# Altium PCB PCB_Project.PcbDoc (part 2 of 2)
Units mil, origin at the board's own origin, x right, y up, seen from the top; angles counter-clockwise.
Board outline 2890 x 2480 mil, 2 copper layers (Top Layer, Bottom Layer), stack 62 mil thick; 127 components, 89 nets, 394 pads, 87 vias.
Unrouted connection lines stored in the file: 1.
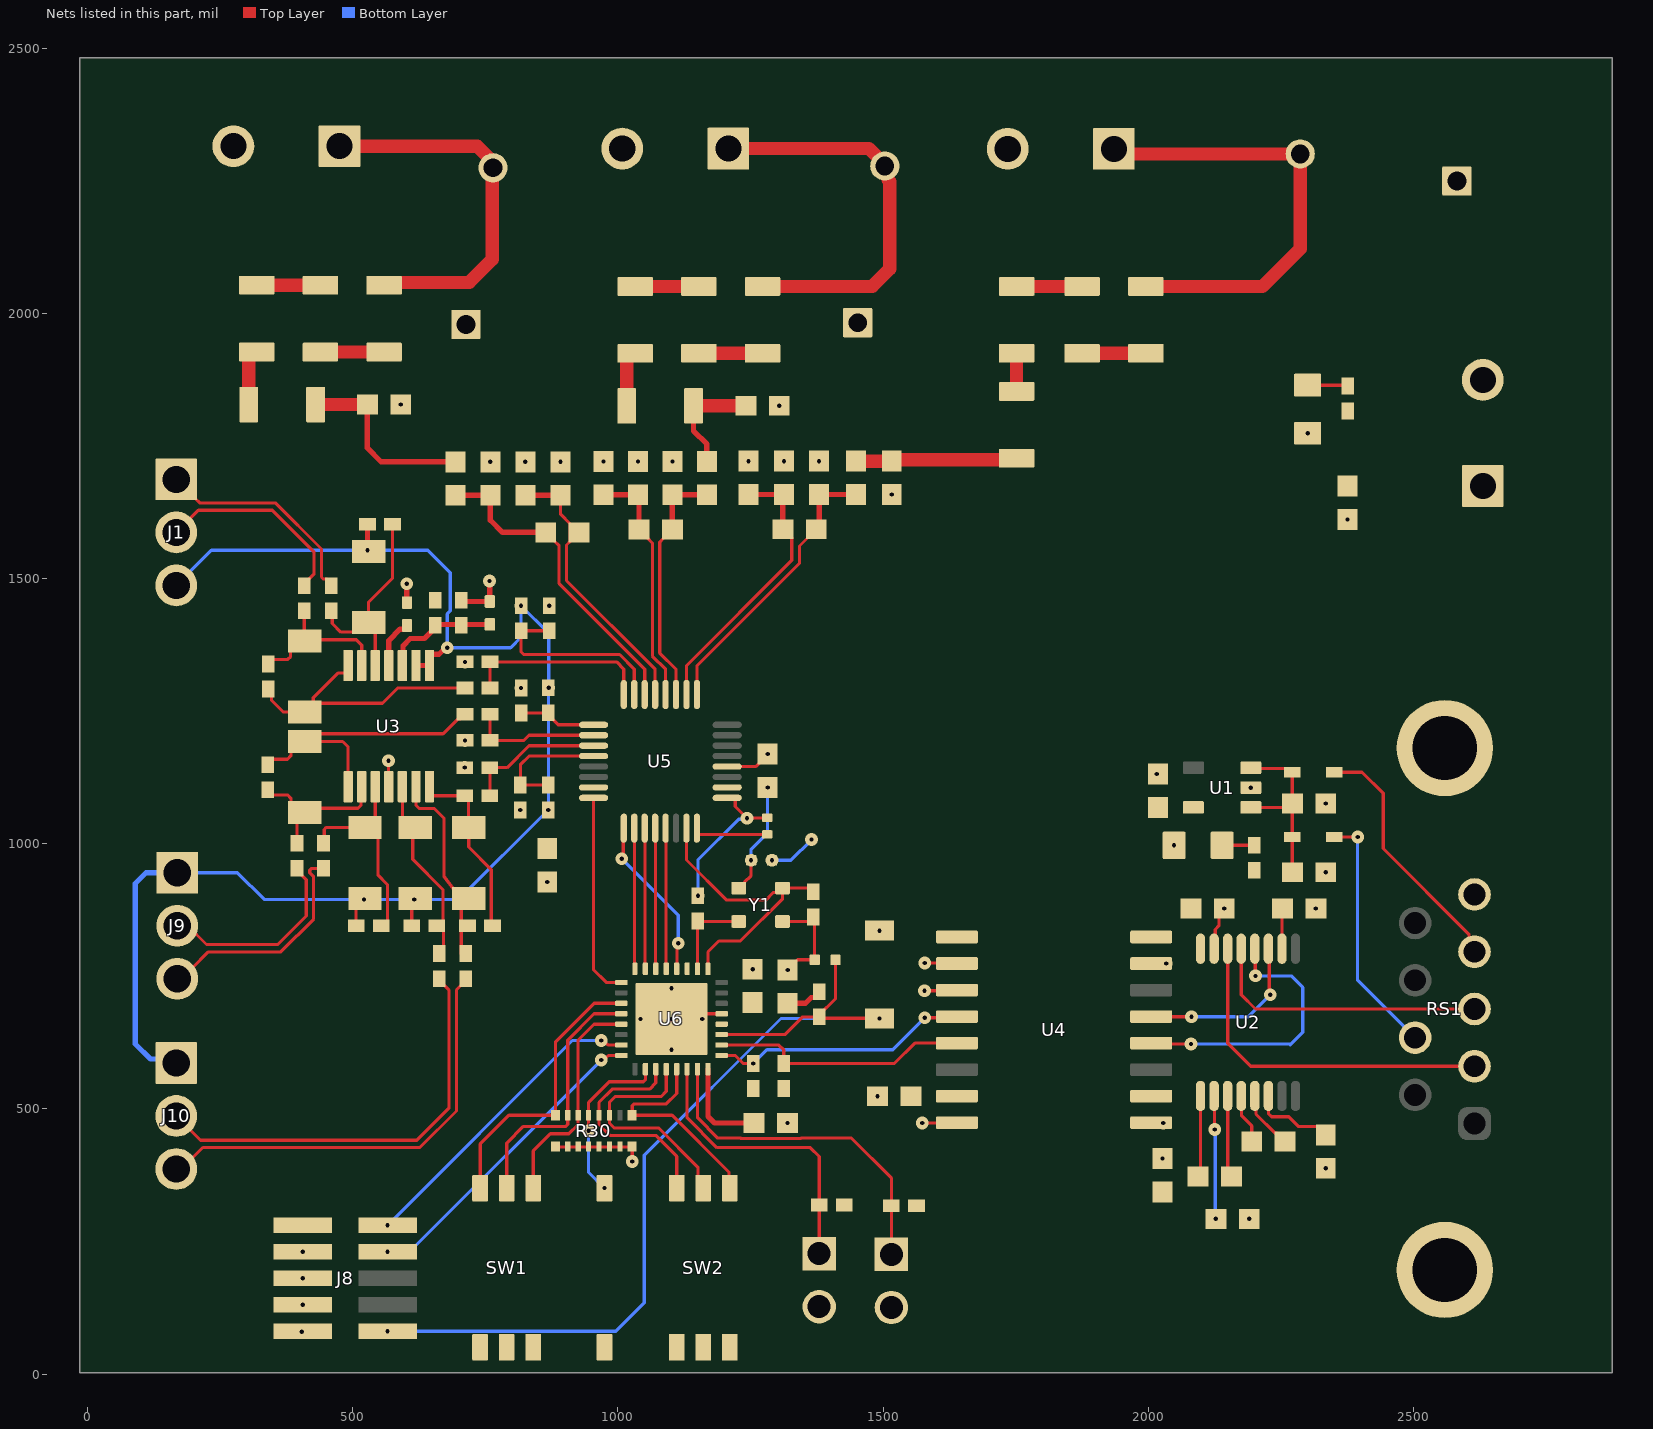
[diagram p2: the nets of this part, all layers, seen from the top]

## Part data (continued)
U3: library part CMP-0128118-1, "Quad, ultra-high-precision (10 μV) zero-drift (0.01 μV/°C) low-input-bias-current op amp 14-TSSOP -40 to 125", Digikey Part Number=296-TLV4387PWRCT-ND, Input Bias Current=60pA, Input Offset Voltage=1uV, Manufacturer="Texas Instruments", Max Dual Supply Voltage=2.75V, Max Supply Voltage=5.5V, Min Dual Supply Voltage=850mV, Min Supply Voltage=1.7V, Mouser Part Number=595-TLV4387PWR, Operating Temperature Range="-40°C to +125°C", Output Current Per Channel=55mA, Voltage Gain=145dB
U4: library part CMP-0094636-1, Digikey Part Number=296-ISO6731DWRCT-ND, Manufacturer="Texas Instruments", Max Supply Voltage=5.5V, Min Supply Voltage=1.71V, Mouser Part Number=595-ISO6731DWR, Operating Temperature Range="-40°C to +125°C"
U5: library part CMP-0085527-2, "8-Channel, 24-Bit, Simultaneously-Sampling, Delta-Sigma ADC, PBS0032A (TQFP-32)", Alternate Manufacturer="Texas Instruments"
U6: library part CMP-0094692-4, "Mixed-Signal Microcontrollers", Frequency_Fixed=80MHz, Manufacturer="Texas Instruments", Max Supply Voltage=3.6V, Min Supply Voltage=1.35V, Operating Temperature Range="-40°C to +125°C"
Y1: library part CMP-0094615-2, "Crystal replacement: Ultra-low Power LVCMOS Oscillator 4-pin, VSON 3.2 x 2.5 x 0.9mm", Frequency Stability=20ppm, Frequency_Fixed=50MHz, Load Capacitance=15pF, Manufacturer="Texas Instruments", Max Supply Current=4mA, Max Supply Voltage=3.465V, Min Supply Voltage=2.375V, Operating Temperature Range="to +135°C", Part Number=CDC6CE05000CDLE

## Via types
v1: diameter 24, hole 8, Top Layer to Bottom Layer, tented both sides, 82 vias
v2: diameter 19.68, hole 7.87, Top Layer to Bottom Layer, 5 vias

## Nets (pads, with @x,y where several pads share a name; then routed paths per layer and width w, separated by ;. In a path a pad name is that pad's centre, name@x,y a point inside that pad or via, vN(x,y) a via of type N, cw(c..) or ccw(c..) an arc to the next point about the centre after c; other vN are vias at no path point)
ACT: J6.1 R20.1 U6.31 | length 649.4
  Top Layer w6: U6.31@1150.12,574.91 1150.12,482.8 1188.1,444.81 1231.55,444.81 1232.58,443.78 1343.95,443.78 1344.98,444.81 1440.35,444.81 1515.49,369.68 R20.1@1515.49,317.28 J6.1@1515.49,225.46
ADS_CS: U5.17 U6.12 | length 312
  Top Layer w6: v1@1011.04,970.79 1009.99,971.84 1009.99,1028.05 U5.17@1011.1,1029.16 ; U6.12@1110.75,763.89 1111.33,764.47 1111.33,809.77 v1(1113.59,812.03)
  Bottom Layer w6: v1(1007.17,971.35) 1113.59,864.92 v1(1113.59,812.03)
ADS_DIN_MSP_DOUT: U5.21 U6.13 | length 265.8
  Top Layer w6: U5.21@1089.84,1029.16 1090.45,1028.55 1090.45,764.5 U6.13@1091.06,763.89
ADS_DOUT_MSP_DIN: U5.20 U6.14 | length 265.8
  Top Layer w6: U5.20@1070.16,1029.16 1070.77,1028.55 1070.77,764.5 U6.14@1071.38,763.89
ADS_DRDY: U5.18 U6.16 | length 265.8
  Top Layer w6: U5.18@1030.79,1029.16 1031.4,1028.55 1031.4,764.5 U6.16@1032.01,763.89
ADS_SYNC_RESET: U5.16 U6.17 | length 386.3
  Top Layer w6: U5.16@954.02,1086.25 954.02,762.25 977.97,738.3 U6.17@1006.42,738.3
GND: C1.2 C4.1 C5.1 C6.2 C9.1 C10.2 C12.1 C14.2 C15.2 C17.1 C23.2 C28.2 C30.2 C33.1 C34.1 C35.1 C38.1 C40.1 C41.1 C44.2 D3.2 J2.2 J3.2 J4.2 J5.2 J6.2 J7.2 J8.3 J8.5 J8.7 J8.9 R8.1 R9.1 R10.1 R16.1 R17.1 R18.1 R26.1 R27.1 R28.1 R30.9 R30.10 R30.11 R30.12 R30.13 R30.14 R30.15 R30.16 R35.1 R36.1 R38.2 R42.1 R44.2 R49.1 R51.2 SW4.1 U3.11 U4.2 U4.3 U4.8 U5.25 U5.28 U6.5 U6.33 Y1.2 | length 1258.4
  Top Layer w6: v1(567.4,1156.13) 567.7,1155.84 567.7,1107.66 U3.11@567.99,1107.36 ; R30.9@877.89,428.25 1026.84,428.25 v1@1026.85,400.75 ; v2(1158.98,669.4) 1158.98,672.4 1165.82,679.24 U6.5@1195.39,679.24 ; U5.25@1205.98,1086.25 1218.58,1086.25 1221.26,1083.56 1221.26,1069.98 v1(1243.39,1047.85) 1243.88,1048.35 1280.88,1048.35 C30.2@1281.38,1048.85 ; U5.28@1205.98,1145.3 1259.64,1145.3 1282.28,1167.94 v1(1282.28,1168.93) ; Y1.2@1310.31,853.17 1359.94,853.17 C6.2@1368.57,861.8 1370.83,859.54 C38.1@1370.83,780.93 1338.98,780.93 1336.69,778.64 1335.7,778.64 1320,762.94 v1(1320,761.96) ; v1(1573.65,473.36) 1638.55,473.36 U4.8@1639.15,473.96 ; v1(1578.03,722.47) 1637.66,722.47 U4.3@1639.15,723.96 ; v1(1578.65,774.82) 1638.28,774.82 U4.2@1639.15,773.96
  Top Layer w10: v1(601.79,1490.16) 602.05,1489.9 602.05,1454.82 C23.2@602.3,1454.56 ; R36.1@704.69,1459.08 707.24,1456.53 C44.2@758.53,1456.53 758.29,1456.77 758.29,1494.79 v1(758.05,1495.03)
  Bottom Layer w6: v1(1150.82,901.52) 1150.82,969.17 1227.6,1045.94 1241.48,1045.94 v1(1243.39,1047.85) ; v1(1290.48,968.56) 1326.12,968.56 v1(1365.17,1007.6)
  other v1: 403.66,79.66 405.53,130.46 405.53,180.46 405.53,230.46 1026.85,400.74 1319.76,473.36 1489.32,523.56 1253.98,763.11 1493.25,835.95 866.71,927.79 816.04,1063.44 711.29,1143.33 711.67,1194.52 817.32,1293.44 711.67,1342.65 870.56,1448.66 2375.71,1611.3 1516.34,1658.17 759.46,1719.82 825.41,1719.83 891.9,1719.83 972.67,1720.71 1037.78,1720.71 1102.67,1720.71 1246.01,1721.16 1312.91,1721.16 1379.33,1721.16 2300.44,1773.74 1304.12,1825.46 590.51,1827.82
  other v2: 1100.91,611.33 1042.83,669.4 1100.91,669.4 1100.91,727.47
GND_ISO_RS: C3.2 C7.2 C8.2 C13.1 C16.1 C20.1 C25.2 D4.2 R29.1 RS1.5 RS1.10 RS1.11 U1.2 U2.15 U4.9 U4.15 | length 83.7
  Top Layer w6: U2.15@2124.04,801.85 2126.28,804.09 2126.28,838.1 2133.06,844.88 2133.06,867.57 v1(2143.14,877.64)
  other v1: 2190.35,292.56 2334.54,387.94 2026.87,406.25 2028.33,473.37 2034.01,773.96 2315.85,877.64 2334.54,946.1 2048.61,996.86 2334.54,1075.59 2193.3,1105.56 2015.8,1131.29
HFXIN: C6.1 U5.23 U6.9 Y1.3 | length 577.1
  Top Layer w6: U5.23@1129.21,1029.16 1129.21,969.11 1204.85,893.48 1278.78,893.48 1293.32,908.01 1302.16,908.01 Y1.3@1310.31,916.16 1361.45,916.16 C6.1@1368.57,909.04 ; U6.9@1169.8,763.89 1169.8,795.87 1190.34,816.4 1230.66,816.4 1310.41,896.15 Y1.3@1310.41,916.06
HFXOUT: C9.2 U6.10 Y1.1 | length 167.3
  Top Layer w6: U6.10@1150.12,763.89 1150.12,841.52 C9.2@1150.82,854.27 1159.63,853.17 Y1.1@1227.64,853.17
IG1: R30.6 SW1.3 U6.21 | length 421.8
  Top Layer w6: SW1.3@840.28,350.46 840.28,420.64 872.7,453.06 907.52,453.06 924.97,470.52 R30.6@924.97,487.99 ; R30.6@924.97,494.68 924.97,629.66 954.87,659.55 U6.21@1006.42,659.55
IG2: R30.7 SW1.2 U6.20 | length 492.9
  Top Layer w6: SW1.2@790.28,350.46 790.28,435.39 821.83,466.94 901.77,466.94 905.29,470.45 R30.7@905.29,487.99 ; R30.7@905.29,490.39 905.29,629.59 954.94,679.24 U6.20@1006.42,679.24
IG4: R30.8 SW1.1 U6.19 | length 536.7
  Top Layer w6: SW1.1@740.28,350.46 740.28,433.86 794.4,487.99 R30.8@882.16,487.99 ; R30.8@882.56,491.34 882.56,626.48 955,698.93 U6.19@1006.42,698.93
IN_Phase_A: C43.2 R51.1 U5.7 | length 367.7
  Top Layer w6: R51.1@870.56,1401.41 C43.2@817.32,1401.41 817.32,1361.75 822.54,1356.53 1003.16,1356.53 1030.79,1328.89 U5.7@1030.79,1281.13
IN_Phase_B: C36.2 R44.1 U5.9 | length 148.5
  Top Layer w6: R44.1@817.32,1246.2 868.1,1246.2 C36.2@868.54,1246.64 868.54,1242.7 887.2,1224.04 U5.9@954.02,1224.04
IN_Phase_C: C27.2 R38.1 U5.12 | length 235.3
  Top Layer w6: C27.2@868.54,1110.69 R38.1@816.03,1110.69 816.03,1148.77 832.25,1164.99 U5.12@954.02,1164.99
IP_Phase_A: C39.2 R35.2 U5.8 | length 354.9
  Top Layer w6: C39.2@758.92,1293.44 R35.2@758.92,1342.65 997.41,1342.65 1011.1,1328.96 U5.8@1011.1,1281.13
IP_Phase_B: C31.2 R49.2 U5.10 | length 248.9
  Top Layer w6: C31.2@758.92,1244.23 R49.2@758.92,1194.52 822.54,1194.52 832.38,1204.36 U5.10@954.02,1204.36
IP_Phase_C: C24.2 R42.2 U5.11 | length 265.8
  Top Layer w6: C24.2@758.53,1090.19 R42.2@758.53,1143.33 790.98,1143.33 832.32,1184.67 U5.11@954.02,1184.67
M0_CLKOUT: U6.11
Meter_RX_PC_TX: RS1.3 U2.13 | length 537.7
  Top Layer w6: U2.13@2175.22,801.85 2175.22,715.08 2202.09,688.22 RS1.3@2615,688.22
Meter_TX_PC_RX: RS1.2 U2.14 | length 661.5
  Top Layer w6: U2.14@2149.63,801.85 2149.63,623.69 2193.11,580.22 RS1.2@2615,580.22
NetC16_2: C16.2 U2.6 | length 157.9
  Top Layer w6: U2.6@2226.4,524.29 2226.4,491.25 2232.78,484.87 2264.93,484.87 2283.37,466.43 2319.04,466.43 C16.2@2334.54,450.93
NetC19_1: C19.1 U2.3 | length 155
  Top Layer w6: U2.3@2149.63,524.29 2149.63,379.49 C19.1@2156.84,372.28
NetC19_2: C19.2 U2.1 | length 153.9
  Top Layer w6: C19.2@2093.84,372.28 2098.45,376.89 U2.1@2098.45,524.29
NetC20_2: C20.2 U2.2 | length 233.1
  Top Layer w6: U2.2@2124.04,524.29 2124.69,523.64 2124.69,461.55 v1(2125.34,460.9)
  Bottom Layer w6: v1(2125.34,460.9) 2126.35,459.9 2126.35,293.57 v1(2127.35,292.56)
NetC21_1: C21.1 U2.5 | length 111.6
  Top Layer w6: U2.5@2200.81,524.29 2203.05,522.05 2203.05,489.97 2239.18,453.84 2242.2,453.84 C21.1@2257.9,438.14
NetC21_2: C21.2 U2.4 | length 94.3
  Top Layer w6: U2.4@2175.22,524.29 2175.95,523.56 2175.95,486.75 2194.91,467.8 C21.2@2194.91,438.14
NetC22_1: C22.1 C39.1 R46.2 U3.7 | length 523.3
  Top Layer w6: R46.2@340.57,1291.47 346.9,1285.13 346.9,1270.24 368.98,1248.17 C22.1@409.88,1248.17 426.45,1264.74 556.02,1264.74 584.71,1293.44 C39.1@711.67,1293.44 ; C22.1@425.7,1263.99 425.7,1275.3 471.92,1321.52 485.36,1321.52 491.22,1327.38 U3.7@491.22,1335.71
NetC22_2: C22.2 R33.2 R46.1 U3.6 | length 301.7
  Top Layer w6: R46.1@340.57,1338.72 349.12,1347.27 377.4,1347.27 382.83,1352.7 382.83,1363.37 401.48,1382.02 C22.2@409.87,1382.02 ; R33.2@408.63,1438.98 408.63,1383.26 C22.2@409.87,1382.02 ; U3.6@516.81,1335.71 516.81,1374.24 506.57,1384.47 412.33,1384.47 C22.2@409.87,1382.02
NetC24_1: C24.1 C37.1 R31.2 U3.14 | length 347.1
  Top Layer w6: U3.14@644.76,1107.36 644.76,1096.05 650.62,1090.19 C24.1@711.29,1090.19 718.45,1083.02 C37.1@718.45,1030.85 ; C37.1@718.68,1030.62 718.68,993.61 761.19,951.11 761.19,850.36 R31.2@765.93,845.62
NetC26_2: C26.2 R34.2 R50.1 U3.5 | length 386.9
  Top Layer w6: R34.2@459.88,1438.98 461.5,1437.35 461.5,1414.99 477.68,1398.81 516.24,1398.81 C26.2@533.05,1415.62 ; C26.2@530,1417.32 530,1455.66 575.14,1500.8 R50.1@575.14,1601.85 ; C26.2@533.05,1405.62 542.4,1396.27 U3.5@542.4,1335.71
NetC29_1: C29.1 C31.1 R39.2 U3.8 | length 579.2
  Top Layer w6: R39.2@339.38,1148.81 339.38,1150.16 348.2,1158.97 377.03,1158.97 383.47,1165.41 383.47,1175.99 400.03,1192.55 C29.1@409.87,1192.55 ; U3.8@491.22,1107.36 491.22,1182.14 480.81,1192.55 C29.1@409.87,1192.55 ; C31.1@711.67,1244.23 702.86,1235.42 698.55,1235.42 670.38,1207.25 424.57,1207.25 C29.1@409.87,1192.55
NetC29_2: C29.2 R39.1 R40.2 U3.9 | length 292.4
  Top Layer w6: R39.1@339.38,1101.57 339.38,1100.4 348.2,1091.59 377.61,1091.59 383.37,1085.83 383.37,1075.35 400.03,1058.69 394.88,1053.54 R40.2@394.88,1000.62 ; C29.2@409.87,1058.69 417.86,1066.68 509.99,1066.68 515.65,1072.35 515.65,1106.21 U3.9@516.81,1107.36
NetC30_1: C30.1 U5.24 | length 142.7
  Top Layer w6: U5.24@1148.9,1029.16 1148.9,1020.03 1151.58,1017.35 C30.1@1281.38,1017.35
NetC32_2: C32.2 R41.2 R43.1 U3.10 | length 366.1
  Top Layer w6: R41.2@444.87,1000.62 446.4,1002.14 446.4,1026.69 450.33,1030.62 C32.2@523.05,1030.62 ; C32.2@528.75,1030.62 547.4,1011.97 547.4,940.94 565.42,922.92 565.42,852.56 R43.1@558.49,845.62 ; C32.2@542.4,1049.28 U3.10@542.4,1107.36
NetC37_2: C37.2 R31.1 R47.2 U3.13 | length 380.1
  Top Layer w6: U3.13@619.17,1107.36 619.25,1107.29 619.25,1072.35 625.33,1066.27 653.69,1066.27 672.1,1047.85 672.1,937.78 690.19,913.9 C37.2@704.69,898.7 ; R47.2@704.69,791.84 704.69,845.46 C37.2@704.69,898.7 ; C37.2@718.68,896.76 C37.2@704.69,898.7
NetC42_2: C42.2 R37.1 R48.2 U3.12 | length 361.4
  Top Layer w6: U3.12@593.58,1107.36 593.58,1049.28 612.24,1030.62 613.05,1030.62 613.05,970.29 670.16,913.18 670.16,854.27 663.78,847.88 661.05,847.88 R37.1@658.62,845.46 ; R37.1@662.27,846.66 671.25,837.68 671.25,800.59 R48.2@663.4,792.74
NetC44_1: C44.1 R32.1 R36.2 U3.3 | length 221
  Top Layer w10: U3.3@593.58,1335.71 594.79,1336.92 594.79,1372.96 608.4,1386.57 635.02,1386.57 648.64,1400.19 648.64,1405.03 656.84,1413.22 704.69,1413.22 C44.1@758.53,1413.22
NetD3_1: D3.1 R6.1 | length 75.8
  Top Layer w6: D3.1@2300.44,1864.29 2374.33,1864.29 R6.1@2375.71,1862.91
NetD4_1: D4.1 R7.1 | length 61
  Top Layer w6: D4.1@2139.16,996.86 R7.1@2200.14,996.86
NetJ1_1: J1.1 R34.1 | length 409.1
  Top Layer w6: J1.1@167.21,1686.85 203.58,1650.48 211.54,1642.51 353.93,1642.51 441,1555.44 441,1502.49 444.51,1498.97 451.06,1498.97 459.87,1490.16 R34.1@459.87,1486.22
NetJ1_2: J1.2 R33.1 | length 381.1
  Top Layer w6: J1.2@167.21,1586.85 209,1628.64 348.18,1628.64 427.12,1549.7 427.12,1508.65 408.63,1490.16 R33.1@408.63,1486.22
NetJ2_1: J2.1 R1.2 R8.2 | length 707.4
  Top Layer w25: J2.1@475,2315 734.76,2315 758.7,2291.06 758.7,2280.03 R8.2@764.46,2274.27 ; R1.2@559.02,2052.82 564.23,2058.04 719.55,2058.04 763.05,2101.54 R8.2@763.05,2271.96
NetJ3_1: J3.1 R11.2 R16.2 | length 756.2
  Top Layer w25: J3.1@1208.13,2310.43 1473.5,2310.43 1503.2,2280.72 R16.2@1503.2,2277.52 ; R11.2@1272.63,2050.46 1479.72,2050.46 1512.7,2083.45 1512.7,2247.82 1508.97,2251.56 R16.2@1508.97,2273.78
NetJ7_1: J7.1 R21.2 R26.2 | length 810.4
  Top Layer w25: 1975.47,2300.46 R26.2@2286.47,2300.46 2286.47,2121.46 2215.47,2050.46 R21.2@1995.47,2050.46
NetJ9_2: J9.2 R40.1 | length 377.3
  Top Layer w6: J9.2@169.18,845.17 188.86,845.17 224.26,809.77 358.67,809.77 412.39,863.48 412.39,931.93 394.88,949.44 R40.1@394.88,953.38
NetJ9_3: J9.3 R41.1 | length 437.6
  Top Layer w6: J9.3@169.18,745.17 169.18,764.85 196.9,764.85 227.91,795.87 364.39,795.87 426.26,857.74 426.26,937.68 419.04,944.89 419.04,949.86 422.56,953.38 R41.1@444.88,953.38
NetJ10_2: J10.2 R48.1 | length 810
  Top Layer w6: J10.2@167.21,486.54 212.88,440.87 620.89,440.87 681.72,501.71 681.72,723.24 672.21,732.75 663.4,741.56 R48.1@663.4,745.5
NetJ10_3: J10.3 R47.1 | length 830.4
  Top Layer w6: J10.3@167.21,386.54 176.93,386.54 217.39,427 626.63,427 695.6,495.96 695.6,724.28 712.88,741.56 R47.1@712.88,745.5
NetR1_1: R1.1 R2.2 | length 120
  Top Layer w25: R2.2@439.02,1926.84 R1.1@559.02,1926.84
NetR2_1: R2.1 R3.2 | length 120
  Top Layer w25: R3.2@319.02,2052.82 R2.1@439.02,2052.82
NetR3_1: R3.1 R4.2 | length 111
  Top Layer w25: R4.2@304.02,1827.82 304.02,1921.62 309.23,1926.84 R3.1@319.02,1926.84
NetR4_1: R4.1 R5.1 R9.2 | length 356.5
  Top Layer w10: R9.2@527.52,1827.82 527.52,1746.07 553.76,1719.83 R5.1@693.84,1719.83
  Top Layer w25: R4.1@430,1827.82 R9.2@527.52,1827.82
NetR11_1: R11.1 R12.2 | length 120
  Top Layer w25: R12.2@1152.63,1924.48 R11.1@1272.63,1924.48
NetR12_1: R12.1 R13.2 | length 120
  Top Layer w25: R13.2@1032.63,2050.46 R12.1@1152.63,2050.46
NetR13_1: R13.1 R14.2 | length 111.9
  Top Layer w25: R14.2@1016.64,1825.46 1016.64,1919.26 1021.86,1924.48 R13.1@1032.63,1924.48
NetR14_1: R14.1 R15.1 R17.2 | length 213.6
  Top Layer w10: R14.1@1142.63,1825.46 1142.63,1778.12 1167.63,1753.12 R15.1@1167.63,1720.71
  Top Layer w25: R14.1@1142.63,1825.46 R17.2@1241.13,1825.46
NetR21_1: R21.1 R22.2 | length 120.5
  Top Layer w25: R22.2@1875,1924.48 R21.1@1995.47,1924.48
NetR22_1: R22.1 R23.2 | length 123.3
  Top Layer w25: R23.2@1751.69,2050.46 R22.1@1875,2050.46
NetR23_1: R23.1 R24.2 | length 71.8
  Top Layer w25: R24.2@1751.69,1852.66 R23.1@1751.69,1924.48
NetR24_1: R24.1 R25.1 R27.2 | length 309.6
  Top Layer w25: R25.1@1448.54,1721.16 1448.54,1724.11 1451.49,1721.16 R27.2@1516.34,1721.16 1519.1,1723.92 1748.93,1723.92 R24.1@1751.69,1726.68
NetR29_2: R29.2 U2.10 | length 76.1
  Top Layer w6: U2.10@2251.99,801.85 2251.99,876.78 R29.2@2252.85,877.64
nRST: C38.2 J8.10 R45.1 SW4.2 U6.3 | length 1767.8
  Top Layer w6: U6.3@1195.39,639.87 1314.67,639.87 1348.13,673.33 R45.1@1379.91,673.33 ; C38.2@1410.2,780.93 1410.2,707.56 1379.91,677.27 R45.1@1379.91,673.33 ; SW4.2@1493.25,670.59 1382.65,670.59 R45.1@1379.91,673.33
  Bottom Layer w6: v1(565.77,80.46) 995.89,80.46 1049.73,134.3 1049.73,412.53 1307.49,670.3 v1(1493.25,670.3)
REACT: J5.1 R19.1 U6.30 | length 554.5
  Top Layer w6: U6.30@1130.43,574.91 1130.43,482.86 1186.5,426.79 1362.76,426.79 1379.49,410.07 R19.1@1379.49,318.65 J5.1@1379.49,226.84
RS232_PORT_DTR: D1.2 RS1.4 | length 479
  Top Layer w6: D1.2@2350.29,1134.71 2402.98,1134.71 2442.8,1094.9 2442.8,990.71 2604.38,829.13 2604.38,806.83 RS1.4@2615,796.22
RS232_PORT_RTS: D2.2 RS1.7 | length 467.5
  Top Layer w6: D2.2@2350.29,1012.48 v1(2394.69,1012.48)
  Bottom Layer w6: v1(2394.69,1012.48) 2394.69,742.52 RS1.7@2503,634.22
Serial_RX: R53.1 U4.5 U6.2 | length 489.1
  Top Layer w6: U6.2@1195.39,620.19 1303.51,620.19 1312.65,611.05 R53.1@1312.65,585.46 1521.34,585.46 1559.84,623.96 U4.5@1639.15,623.96
Serial_RX_ISO: U2.12 U4.12 | length 531.6
  Top Layer w6: U4.12@2005.29,623.96 2007.15,622.09 v1(2080.5,622.09) ; U2.12@2200.81,801.85 2201.45,801.21 2201.45,751.29 v1(2202.09,750.65)
  Bottom Layer w6: v1(2080.5,622.09) 2266.32,622.09 2267.74,620.67 2291.18,644.11 2291.18,728.97 2269.5,750.65 v1(2202.09,750.65)
Serial_TX: R52.1 U4.4 U6.1 | length 486.6
  Top Layer w6: U6.1@1195.39,600.5 1221.26,600.5 1236.3,585.46 v1(1255,585.46) ; v1(1578.65,671.62) 1636.81,671.62 U4.4@1639.15,673.96
  Bottom Layer w6: v1(1255,585.46) 1280.87,611.33 1518.36,611.33 v1(1578.65,671.62)
Serial_TX_ISO: U2.11 U4.13 | length 330.1
  Top Layer w6: U4.13@2005.29,673.96 2005.61,673.63 v1(2081.4,673.63) ; U2.11@2226.4,801.85 2228.14,800.11 2228.14,716.82 v1(2229.87,715.08)
  Bottom Layer w6: v1(2081.4,673.63) 2188.42,673.63 v1(2229.87,715.08)
SPI_SCK: U5.19 U6.15 | length 265.8
  Top Layer w6: U5.19@1050.47,1029.16 1051.08,1028.55 1051.08,764.5 U6.15@1051.69,763.89
SW_INT: R30.5 SW3.1 U6.26 | length 319.1
  Top Layer w6: v1@944.62,458.76 R30.5@944.62,487.95 ; R30.5@944.66,487.99 944.66,512.1 983.52,550.96 1048.18,550.96 1051.69,554.48 U6.26@1051.69,574.91
  Bottom Layer w6: v1(944.59,458.73) 944.59,380.37 v1(974.5,350.46)
SWCLK: J8.4 U6.24 | length 593.9
  Top Layer w6: v1(968.52,591.92) 973.39,591.92 981.97,600.5 U6.24@1006.42,600.5
  Bottom Layer w6: v1(565.77,230.46) 607.06,230.46 v1(968.52,591.92)
SWDIO: J8.2 U6.23 | length 588.5
  Top Layer w6: v1(968.52,628.8) 973.39,628.8 982.01,620.19 U6.23@1006.42,620.19
  Bottom Layer w6: v1(565.77,280.46) 914.11,628.8 v1(968.52,628.8)
TPS709_IN: C3.1 C8.1 D1.1 D2.1 U1.1 U1.3 | length 351.6
  Top Layer w6: U1.1@2193.3,1068.16 2264.12,1068.16 C8.1@2271.55,1075.59 ; U1.3@2193.3,1142.97 2194.7,1141.56 2264.7,1141.56 D1.1@2271.55,1134.71 C8.1@2271.55,1075.59 ; C3.1@2271.55,946.1 D2.1@2271.55,1012.48 C8.1@2271.55,1075.59
V_Phase_A_N: C2.2 C4.2 R10.2 U5.5 | length 545.1
  Top Layer w6: R10.2@891.9,1656.83 891.9,1620.75 910.11,1602.55 C2.2@910.11,1571.15 ; C2.2@926.79,1586.85 925.81,1586.85 C2.2@910.11,1571.15 ; U5.5@1070.16,1281.13 1070.16,1328.77 903.02,1495.9 903.02,1563.08 910.11,1570.16 C2.2@910.11,1571.15
  Top Layer w10: C4.2@825.41,1656.83 R10.2@891.9,1656.83
V_Phase_A_P: C1.1 C2.1 R5.2 U5.6 | length 610.1
  Top Layer w6: C2.1@863.8,1586.85 864.78,1586.85 880.49,1571.15 880.49,1570.16 889.15,1561.5 889.15,1490.16 1050.47,1328.83 U5.6@1050.47,1281.13
  Top Layer w10: R5.2@693.84,1656.84 C1.1@759.46,1656.83 759.46,1609.75 782.36,1586.85 C2.1@863.8,1586.85
V_Phase_B_N: C11.2 C12.2 R18.2 U5.4 | length 463.8
  Top Layer w6: C11.2@1039.67,1592.23 1040.66,1592.23 1056.36,1576.53 1056.36,1575.55 1065.04,1566.87 1065.04,1353.5 1089.84,1328.7 U5.4@1089.84,1281.13
  Top Layer w10: R18.2@972.67,1657.72 C12.2@1037.78,1657.72 1039.67,1655.82 C11.2@1039.67,1592.23
V_Phase_B_P: C10.1 C11.1 R15.2 U5.3 | length 464.6
  Top Layer w6: C11.1@1102.67,1592.23 1101.68,1592.23 1085.98,1576.53 1085.98,1575.55 1078.91,1568.48 1078.91,1359.25 1109.53,1328.64 U5.3@1109.53,1281.13
  Top Layer w10: C11.1@1102.67,1592.23 C10.1@1102.67,1657.72 R15.2@1167.63,1657.72
V_Phase_C_N: C17.2 C18.2 R28.2 U5.2 | length 534.4
  Top Layer w6: U5.2@1129.21,1281.13 1129.21,1335.54 1327.61,1533.94 1327.61,1573.47 ; C18.2@1310.9,1592.68 1311.89,1592.68 1327.59,1576.98 1327.59,1573.48
  Top Layer w10: R28.2@1246.01,1658.17 C17.2@1312.91,1658.17 1310.9,1656.16 C18.2@1310.9,1592.68
V_Phase_C_P: C15.1 C18.1 R25.2 U5.1 | length 541.7
  Top Layer w6: U5.1@1148.9,1281.13 1148.9,1334.93 1342.4,1528.44 1342.4,1561.19 C18.1@1373.9,1592.68
  Top Layer w10: C18.1@1373.9,1592.68 1379.33,1598.11 C15.1@1379.33,1658.17 R25.2@1448.54,1658.17
VCC: C5.2 C14.1 C23.1 C28.1 C34.2 C35.2 C40.2 C41.2 J4.1 J8.1 R6.2 R19.2 R20.2 R32.2 R45.2 R52.2 R53.2 SW1.4 SW1.5 SW1.6 SW2.4 SW2.5 SW2.6 SW3.2 U3.4 U4.1 U4.7 U5.15 U5.26 U6.4 Y1.4 | length 379.2
  Top Layer w6: Y1.4@1227.64,916.16 1229.6,916.16 1238.42,924.97 1238.42,926.94 1251.11,939.63 v1(1251.11,968.56)
  Top Layer w10: U3.4@567.99,1335.71 567.99,1383.1 589.34,1404.44 597.46,1404.44 602.3,1409.28 C23.1@602.3,1411.25 ; C35.2@1320,698.97 1353.7,698.97 1364.57,709.83 1373.1,709.83 1379.91,716.64 R45.2@1379.91,720.58
  Bottom Layer w6: v1(1251.11,968.56) 1251.11,989.3 1282.28,1020.48 v1(1282.28,1105.93)
VCC_ISO_RS: C7.1 C13.2 C25.1 R7.2 U1.5 U2.16 U4.10 U4.16
VCM: C26.1 C27.1 C32.1 C36.1 C42.1 C43.1 J1.3 J9.1 J10.1 R37.2 R43.2 R50.2 U3.1 U3.2 | length 2853
  Top Layer w6: R43.2@506.38,845.46 506.38,880.09 v1(521.08,894.79) C32.1@523.05,896.76 ; R37.2@611.38,845.46 611.38,890.09 v1(616.09,894.79) C42.1@618.06,896.76
  Top Layer w10: C26.1@527.9,1553.29 R50.2@527.9,1601.85 ; U3.2@619.17,1335.71 U3.1@644.77,1335.71 644.77,1352.97 648.62,1356.83 662.1,1356.83 674.44,1369.17 v1(678.23,1369.17)
  Bottom Layer w6: J1.3@150.17,1486.85 J1.3@167.21,1486.85 233.51,1553.15 v1(528.03,1553.15) 641.78,1553.15 683.93,1511 683.93,1438.84 678.23,1433.14 v1(678.23,1369.17) 797.58,1369.17 817.32,1388.92 v1(817.32,1448.65) 869.48,1396.5 v1(869.48,1294.08) 869.01,1293.61 869.01,1063.91 v1(868.54,1063.44) 699.89,894.79 v1(616.09,894.79) v1(521.08,894.79) 332.88,894.79 282.5,945.17 J9.1@169.18,945.17
  Bottom Layer w10: J10.1@167.21,586.54 159.88,593.87 118.7,593.87 90,622.57 90,924.83 110.33,945.17 J9.1@169.18,945.17
VCORE: C33.2 U6.32 | length 181.4
  Top Layer w10: U6.32@1169.8,574.91 1169.8,485.56 1182.01,473.36 C33.2@1256.77,473.36
VG1: R30.1 SW2.3 U6.29 | length 415.2
  Top Layer w6: R30.1@1026.84,487.99 1102.1,487.99 1209.14,380.95 1209.14,352.16 SW2.3@1210.84,350.46 ; R30.1@1026.89,487.99 1026.89,505.83 1030.4,509.34 1091.29,509.34 1110.75,528.8 U6.29@1110.75,574.91
VG2: R30.3 SW2.2 U6.28 | length 441.9
  Top Layer w6: U6.28@1091.06,574.91 1091.06,532.76 1081.52,523.21 995.01,523.21 984.03,512.23 R30.3@984.03,487.99 984.03,472.56 992.82,463.76 1076.89,463.76 1150.82,389.83 1150.82,360.48 SW2.2@1160.84,350.46
VG4: R30.4 SW2.1 U6.27 | length 421.3
  Top Layer w6: U6.27@1071.38,574.91 1071.38,548.81 1059.66,537.09 989.26,537.09 964.34,512.17 964.34,470.37 984.82,449.89 1071.14,449.89 1110.84,410.19 SW2.1@1110.84,350.46
pads on no net: J8.6 J8.8 R30.2 RS1.1 RS1.6 RS1.8 RS1.9 U1.4 U2.7 U2.8 U2.9 U4.6 U4.11 U4.14 U5.13 U5.14 U5.22 U5.27 U5.29 U5.30 U5.31 U5.32 U6.6 U6.7 U6.8 U6.18 U6.22 U6.25

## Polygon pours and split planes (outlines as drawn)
VCC_ISO_RS on Top Layer "TOP_LAYER_VCC_ISO_RS_P003" (solid, remove dead copper, pour order 3): 2869.5,1248.46 2815.1,1302.86 2070.49,1302.86 2009.42,1241.79 2009.42,81.33 2074.8,15.95 2826.99,15.95 2869.5,58.46
VCC on Top Layer "TOP_LAYER_VCC_P001" (solid, remove dead copper, pour order 1): 1630.66,1370.32 1728.8,1468.46 2829.5,1468.46 2869.5,1508.46 2869.5,2388.46 2819.5,2438.46 339.5,2438.46 220.07,2319.03 205.23,99.86 294.5,8.46 1556.46,8.46 1630.66,82.66
GND_ISO_RS on Bottom Layer "BOTTOM_LAYER_GND_ISO_RS_P004" (solid, remove dead copper, pour order 4): 2869.5,1248.46 2815.1,1302.86 2070.49,1302.86 2009.42,1241.79 2009.42,81.33 2074.8,15.95 2826.99,15.95 2869.5,58.46
GND on Bottom Layer "BOTTOM_LAYER_GND_P002" (solid, remove dead copper, pour order 2): 1630.66,1370.32 1728.8,1468.46 2829.5,1468.46 2869.5,1508.46 2869.5,2388.46 2819.5,2438.46 339.5,2438.46 220.07,2319.03 205.23,99.86 294.5,8.46 1556.46,8.46 1630.66,82.66

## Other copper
Top Layer:
  pour cut-out: 1119.5,978.46 1129.85,988.81 1433.16,988.81 1443.09,978.88 1443.09,838.04 1396.78,803.07 1297.89,803.07 1205.44,803.07 1175.68,773.31 1135.53,773.31 1117.97,790.87
Bottom Layer:
  pour cut-out: 1119.53,978.49 1129.88,988.84 1433.19,988.84 1443.12,978.91 1443.12,838.04 1396.78,803.07 1205.44,803.07 1175.71,773.34 1135.56,773.34 1118,790.9

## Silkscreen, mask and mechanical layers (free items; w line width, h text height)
Top Overlay:
  text "GND" at 2838.5,1843.16 h20 r90
  text "TIDA-011013" at 2140.67,1793.72 h50 r270
  text "I_A_P" at 329.5,1718.35 h20
  text "I_A_N" at 330.45,1658.78 h20
  text "+3V3" at 2836.3,1631.74 h20 r90
  text "VCM" at 332.96,1581.55 h30
  text "VCM" at 350.37,822.4 h30
  text "I_B_P" at 345.38,768.55 h20
  text "I_B_N" at 344.37,703.3 h20
  text "VCM" at 338.88,567.84 h30
  text "I_C_N" at 335.5,479.7 h20
  text "I_C_P" at 335.5,380.33 h20
  text "ACT" at 1588.37,219.46 h20
  text "REACT" at 1309.24,203.71 h20 r90
  text "GND" at 1414.3,31.46 h20
M1 Board Outline:
  lines w10: -15,0.43 2880.5,0.43 2880.5,2480.43 -15,2480.43 -15,0.43
M9 Title Sheet:
  drawing of 63 lines, arcs and shapes, not listed
  text "1" at 1389.5,18376 h70
  text "2" at 5384.5,18376 h70
  text "3" at 9379.5,18376 h70
  text "4" at 13380.51,18376 h70
  text "5" at 17378.84,18376 h70
  text "6" at 21377.18,18376 h70
  text "7" at 25378.84,18376 h70
  text "8" at 29373.84,18376 h70
  text "A" at -467.5,15978 h70
  text "A" at 31232.5,15978 h70
  text "B" at -467.5,10978 h70
  text "B" at 31232.5,10978 h70
  text "C" at -467.5,5978 h70
  text "C" at 31232.5,5978 h70
  text "D" at -467.5,978 h70
  text "D" at 31232.5,978 h70
  text "PROJECT TITLE:" at 28147.5,268.61 h45
  text ".PRJ_Title" at 28197.5,135.28 h70
  text "DESIGNED FOR:" at 28147.5,-32.39 h45
  text ".PRJ_Customer" at 28197.5,-172.39 h70
  text "FILE NAME:" at 28147.5,-332.39 h45
  text ".PCB_File_Name_No_Path" at 28197.5,-452.39 h70
  text "Texas Instruments (TI) and/or its licensors do not warrant the accuracy or completeness of this specification" at 23178,-614.23 h45
  text "ENGINEER:" at 28147.5,-622.39 h45
  text "LAYOUT BY:" at 29652.5,-622.39 h45
  text "or any information contained therein. TI and/or its licensors do not warrant that this design will meet" at 23133.01,-726.89 h45
  text ".PRJ_Engineer" at 28197.5,-777.38 h70
  text ".PCB_Layout" at 29703,-777.38 h70
  text "the specifications, will be suitable for your application or fit for any particular purpose, or will operate in" at 23133.01,-839.56 h45
  text ".Layer_Name" at 577,-858.49 h60
  text "ALTIUM DESIGNER VERSION:" at 29652.5,-932.39 h45
  text "an implementation. TI and/or its licensors do not warrant that the design is production worthy. You should" at 23133.01,-952.22 h45
  text "completely validate and test your design implementation to confirm the system functionality for your application." at 23178,-1064.89 h45
  text ".print_Scale" at 28197.5,-1065.72 h70
  text ".Application_BuildNumber" at 29703,-1065.72 h70
  text "1" at 1389.5,-1319 h70
  text "2" at 5384.5,-1319 h70
  text "3" at 9379.5,-1319 h70
  text "4" at 13380.51,-1319 h70
  text "5" at 17378.84,-1319 h70
  text "6" at 21377.18,-1319 h70
  text "7" at 25378.84,-1319 h70
  text "8" at 29373.84,-1319 h70
M10 Fab Notes:
  drawing of 189 lines, arcs and shapes, not listed
  text "DESIGN INFORMATION" at 29188.02,6365.17 h60
  text "MIN. TRACK WIDTH:" at 28543.46,6233.05 h60
  text "8" at 29639.7,6233.05 h60
  text "MIL" at 29794.46,6233.05 h60
  text "MIN. CLEARANCE:" at 28543.46,6108.92 h60
  text "7.874" at 29468.5,6108.92 h60
  text "MIL" at 29794.46,6108.92 h60
  text "MIN. VIA PAD SIZE:" at 28543.46,5984.8 h60
  text "24" at 29609.71,5984.8 h60
  text "MIL" at 29794.46,5984.8 h60
  text "0.05mm (2MIL)" at 29238.46,5854.9 h60
  text "MINIMUM ANNULAR RING" at 28214.23,5846.67 h60
  text "EXTERNAL" at 29946.46,5846.67 h60
  text "PER" at 28414.23,5736.55 h60
  text "IPC-D-275 CLASS 2 LEVEL C" at 28634.23,5736.54 h60
  text "MIL, HOLES" at 30122.46,5636.07 h60
  text "+/-" at 29730,5627.48 h60
  text "+/-" at 30584,5627.48 h60
  text "REGISTRATION TOLERANCES:" at 28214.23,5626.42 h60
  text "METAL" at 29414,5626.42 h60
  text "5" at 29990.2,5626.42 h60
  text "3" at 30823.2,5626.42 h60
  text "MIL" at 30939.46,5626.42 h60
  text "HOLE SIZE TOLERANCE (UNLESS OTHERWISE SPECIFIED):" at 28214.23,5528.1 h60
  text "+/-" at 30584,5525.23 h60
  text "3" at 30823.2,5524.17 h60
  text "MIL" at 30939.46,5524.17 h60
  text "MATERIAL:" at 28139.46,5386.52 h60
  text "FR-4 High Tg" at 29125.9,5258 h60
  text "X" at 28981.46,5250.01 h60
  text "FR-4" at 28560.46,5245.49 h60
  text "OTHER" at 30048.46,5245.49 h60
  text "62 MIL (1.6mm) +/-10%" at 28880.56,5102.46 h60
  text "X" at 28760.46,5100.01 h60
  text "THICKNESS:" at 28214.23,5094.24 h60
  text "OTHER" at 30165.46,5094.24 h60
  text "TOLERANCE:" at 28214.23,4955.92 h60
  text "X" at 29062.46,4955.92 h60
  text "ANSI IPC-6012 TYPE 3 CLASS 2" at 29240.48,4955.92 h60
  text "OTHER +/-" at 29240.46,4811.73 h60
  text "BOW & TWIST:" at 28214.23,4666.54 h60
  text "X" at 29062.46,4666.54 h60
  text "ANSI IPC-6012 TYPE 3 CLASS 2" at 29240.48,4666.54 h60
  text "OTHER +/-" at 29240.46,4519.85 h60
  text "DRILLING:" at 28139.46,4389.23 h60
  text "NC_DRILL FILES" at 29900.46,4284.04 h60
  text "REFERENCE:" at 28214.23,4280.1 h60
  text "X" at 28871.46,4280.01 h60
  text "AS SHOWN" at 29049.46,4280.1 h60
  text "X" at 29772.46,4280.1 h60
  text "OTHER" at 30198.46,4137.85 h60
  text "PTH COPPER THICKNESS:" at 28213.91,4134.32 h60
  text "X" at 29353.14,4134.32 h60
  text "20-30 um" at 29481.14,4134.32 h60
  text "BOARD FINISH:" at 28139.46,3986.73 h60
  text "SILKSCREEN:" at 28294.68,3876.6 h60
  text "X" at 29252.46,3876.6 h60
  text "TOP" at 29369.46,3876.6 h60
  text "X" at 29762.46,3876.6 h60
  text "BOTTOM" at 29880.46,3876.6 h60
  text "SILKSCREEN COLOR:" at 28294.68,3721.41 h60
  text "X" at 29251.46,3721.41 h60
  text "WHITE" at 29369.46,3721.41 h60
  text "OTHER" at 29880.46,3721.41 h60
  text "X" at 29382.46,3577.96 h60
  text "GREEN" at 29500.46,3577.96 h60
  text "OTHER" at 30118.46,3577.96 h60
  text "SOLDER RESIST COLOR:" at 28294.68,3571.1 h60
  text "X" at 29382.46,3423.71 h60
  text "MATTE" at 29500.46,3423.71 h60
  text "SEMI-GLOSS" at 30118,3423.07 h60
  text "IMMERSION GOLD (ENIG)" at 29200.46,3250.94 h60
  text "ENEPIG" at 30538,3243.72 h60
  text "SURFACE FINISH:" at 28139.46,3242.72 h60
  text "X" at 29022.46,3242.72 h60
  text "IMM. TIN/SILVER OR EQUIV" at 28469,3105.4 h60
  text "OTHER" at 29900.46,3101.47 h60
  text "ARRAY/PANEL:" at 28139.46,2946.09 h60
  text "CUT AND TRIM PER M1 BOARD OUTLINE" at 29200.46,2937.87 h60
  text "N.C. ROUTE" at 29200.46,2801.9 h60
  text "X" at 29888.46,2801.9 h60
  text "V. SCORE" at 30066.46,2801.9 h60
  text "CERTIFICATION:" at 28139.46,2672.77 h60
  text "MATERIALS AND WORKMANSHIP FOR ALL PCBS" at 28864.46,2672.77 h60
  text "TO MEET OR EXCEED THE REQUIREMENTS OF:" at 28864.46,2578.71 h60
  text "X" at 28501.97,2450.08 h60
  text "ANSI IPC-A-600F CLASS ->" at 28629.96,2450.08 h60
  text "X" at 30277.97,2450.08 h60
  text "2" at 30387.96,2450.08 h60
  text "1" at 30072.96,2448.58 h60
  text "3" at 30741.96,2448.58 h60
  text "X" at 29313.97,2302.39 h60
  text "RoHS" at 29441.96,2302.39 h60
  text "OTHER" at 30086.36,2302.39 h60
  text "PER ORDER" at 30483.42,2302.39 h60
  text "ALL BOARDS MUST MEET OR EXCEED UL94-V0 REQUIREMENTS." at 28167,2148.57 h60
  text "PCB MUST BEAR THE UL94V-0 UL REGISTERED MATERIAL ID NUMBER" at 28167,2032.5 h60
  text "ADDITIONAL REQUIREMENTS:" at 28139.46,1863.08 h60
  text "MICROSECTION:" at 28214.23,1755.95 h60
  text "YES" at 29119.96,1755.95 h60
  text "REQUIRED" at 29981.46,1611.62 h60
  text "BARE BOARD ELEC. TEST:" at 28214.23,1608.76 h60
  text "NONE" at 29519.96,1608.76 h60
  text "X" at 29863.46,1608.76 h60
  text "PER ORDER" at 30573.46,1608.76 h60
  text "XX MIL VIAS REQUIRE NON-CONDUCTIVE FILL AND PLANARIZE" at 28382.38,1403.82 h59
  text "XX MIL VIAS REQUIRE CONDUCTIVE FILL AND PLANARIZE" at 28390.38,1299.84 h60
  text "OUTER XX MIL TRACES REQUIRE 50 OHM SINGLE-ENDED IMPEDANCE" at 28389.39,1136.46 h58
  text "LAYER 2 & 3 (INNER LAYERS) XX MIL WIDE, XX MIL SPACE / TRACES REQUIRE 100 OHM DIFFERENTIAL IMPEDANCE" at 28381.39,900.74 h60
M12 Stackup:
  drawing of 191 lines, arcs and shapes, not listed
  text "Layer" at 26553.88,18012.74 h60
  text "Name" at 26963.79,18012.74 h60
  text "Material" at 27893.54,18012.74 h60
  text "Thickness" at 28753.3,18012.74 h60
  text "Constant" at 29403.14,18012.74 h60
  text "Board Layer Stack" at 29973,18012.74 h60
  text "Top Overlay" at 26963.79,17892.74 h60
  text "Top Solder" at 26963.79,17772.74 h60
  text "Solder Resist" at 27893.54,17772.74 h60
  text "0.40mil" at 28753.3,17772.74 h60
  text "3.5" at 29403.14,17772.74 h60
  text "1" at 26553.88,17652.74 h60
  text "Top Layer" at 26963.79,17652.74 h60
  text "1.40mil" at 28753.3,17652.74 h60
  text "Dielectric1" at 26963.79,17532.74 h60
  text "FR-4 High Tg" at 27893.54,17532.74 h60
  text "59.20mil" at 28753.3,17532.74 h60
  text "4.8" at 29403.14,17532.74 h60
  text "2" at 26553.88,17412.74 h60
  text "Bottom Layer" at 26963.79,17412.74 h60
  text "1.40mil" at 28753.3,17412.74 h60
  text "Bottom Solder" at 26963.79,17292.74 h60
  text "Solder Resist" at 27893.54,17292.74 h60
  text "0.40mil" at 28753.3,17292.74 h60
  text "3.5" at 29403.14,17292.74 h60
  text "Bottom Overlay" at 26963.79,17172.74 h60
M17 Embedded Cavity:
  text ".Layer_Name" at 577,-858.49 h60
M18 Embedded Assembly:
  text ".Layer_Name" at 577,-858.49 h60
M19 Embedded Keepout:
  text ".Layer_Name" at 587,-848.49 h60

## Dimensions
0,0 to 2875,2 on M2 Board Dimensions
0,0 to -15,2482 on M2 Board Dimensions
